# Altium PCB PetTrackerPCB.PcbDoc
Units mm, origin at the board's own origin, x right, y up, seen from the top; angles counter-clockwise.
Board outline 116.71 x 58.42 mm, 4 copper layers (Top Layer, GND Plane, PWR Plane, Bottom Layer), stack 0.868 mm thick; 37 components, 41 nets, 216 pads, 121 vias.
Unrouted connection lines stored in the file: 37.
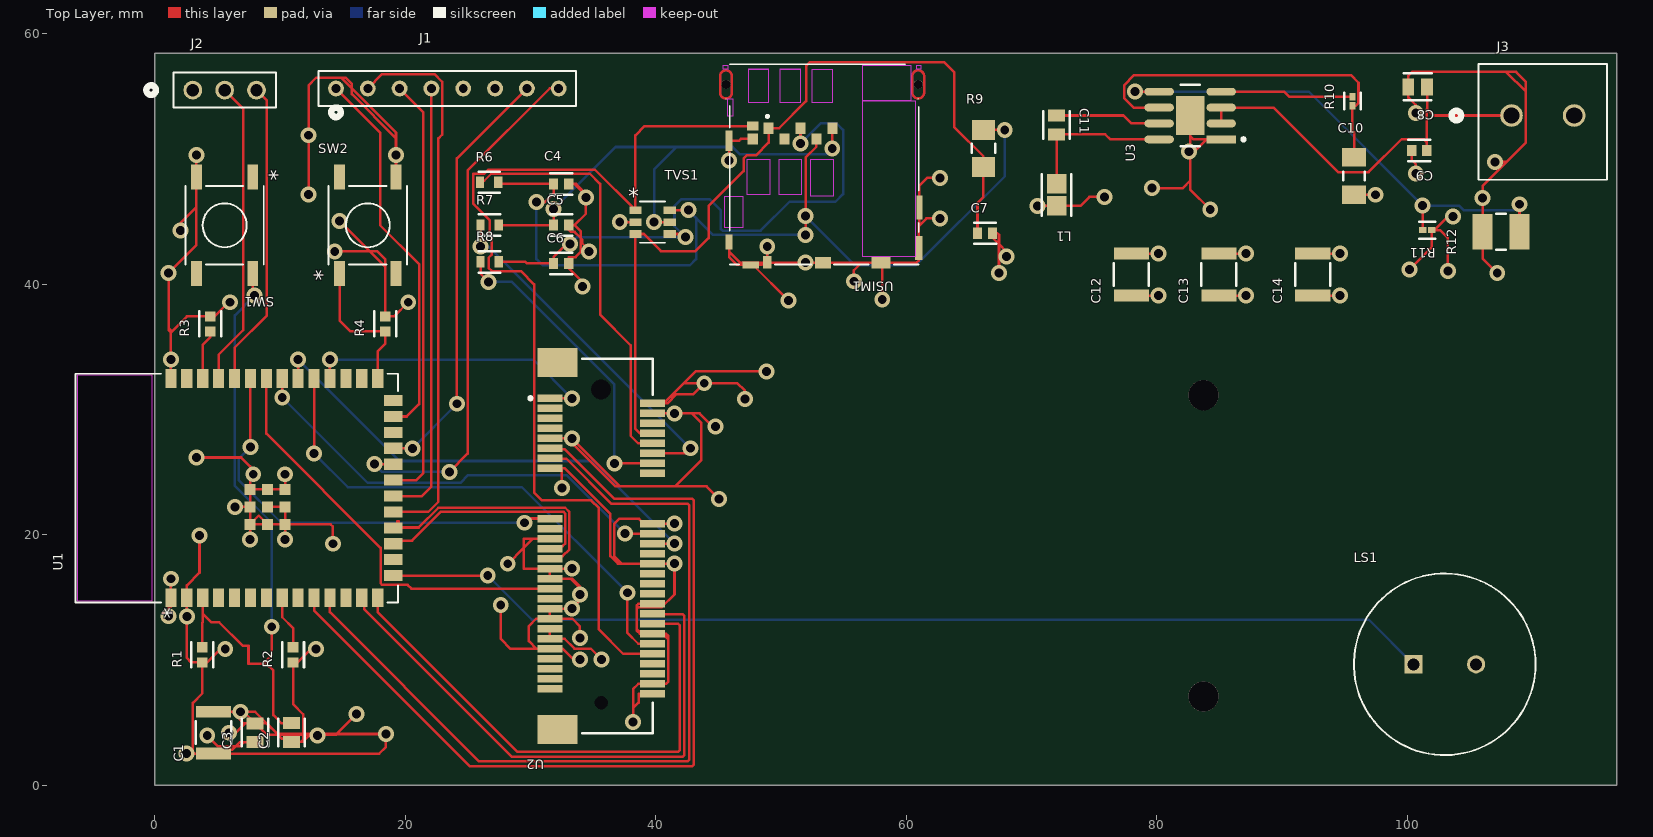
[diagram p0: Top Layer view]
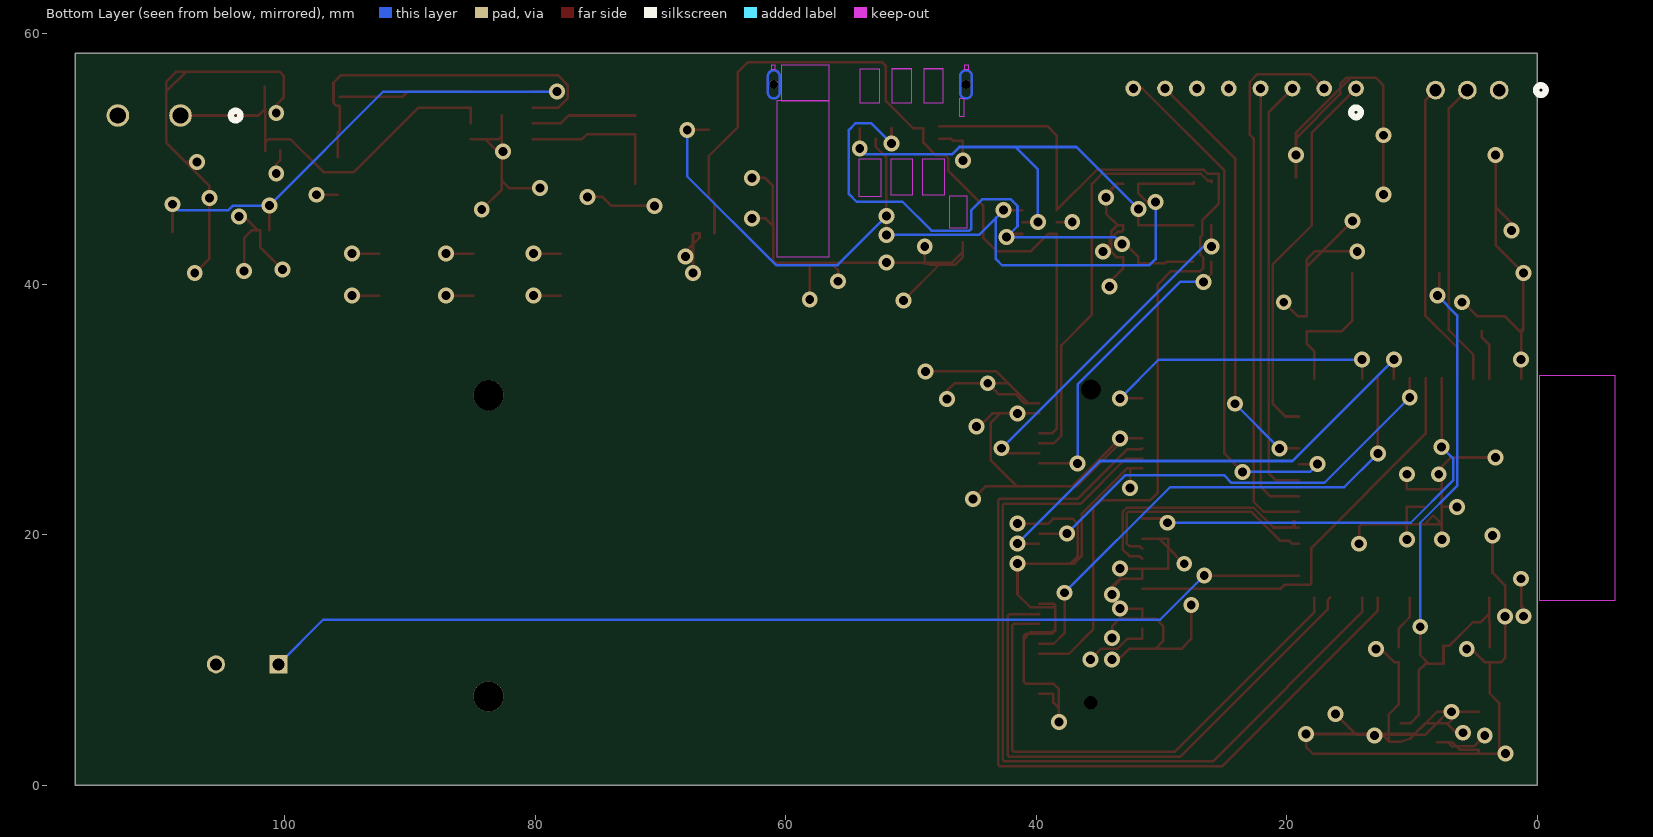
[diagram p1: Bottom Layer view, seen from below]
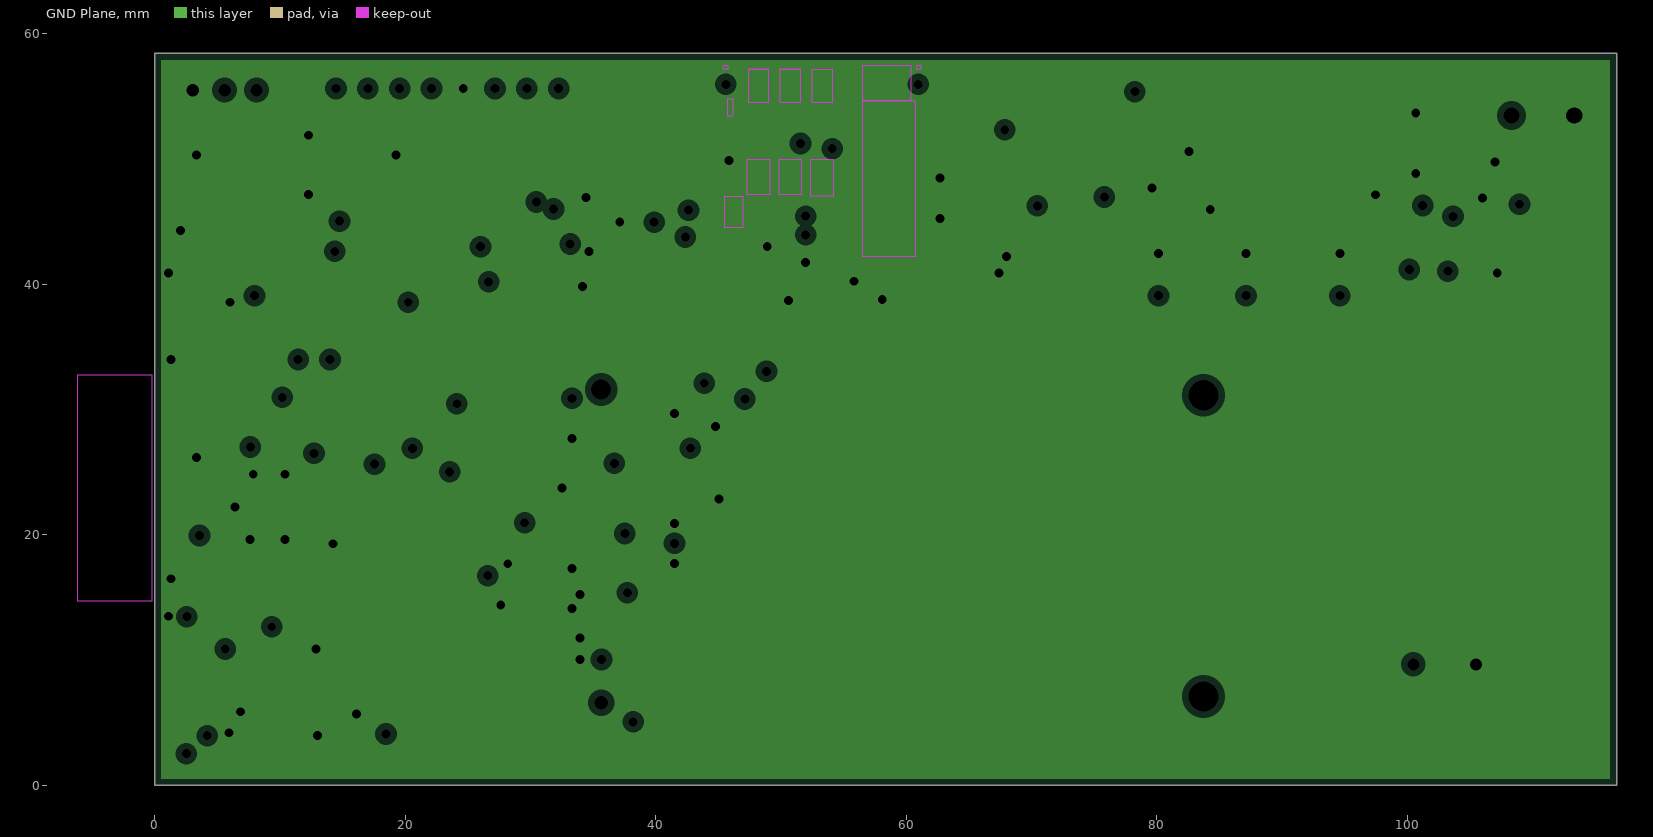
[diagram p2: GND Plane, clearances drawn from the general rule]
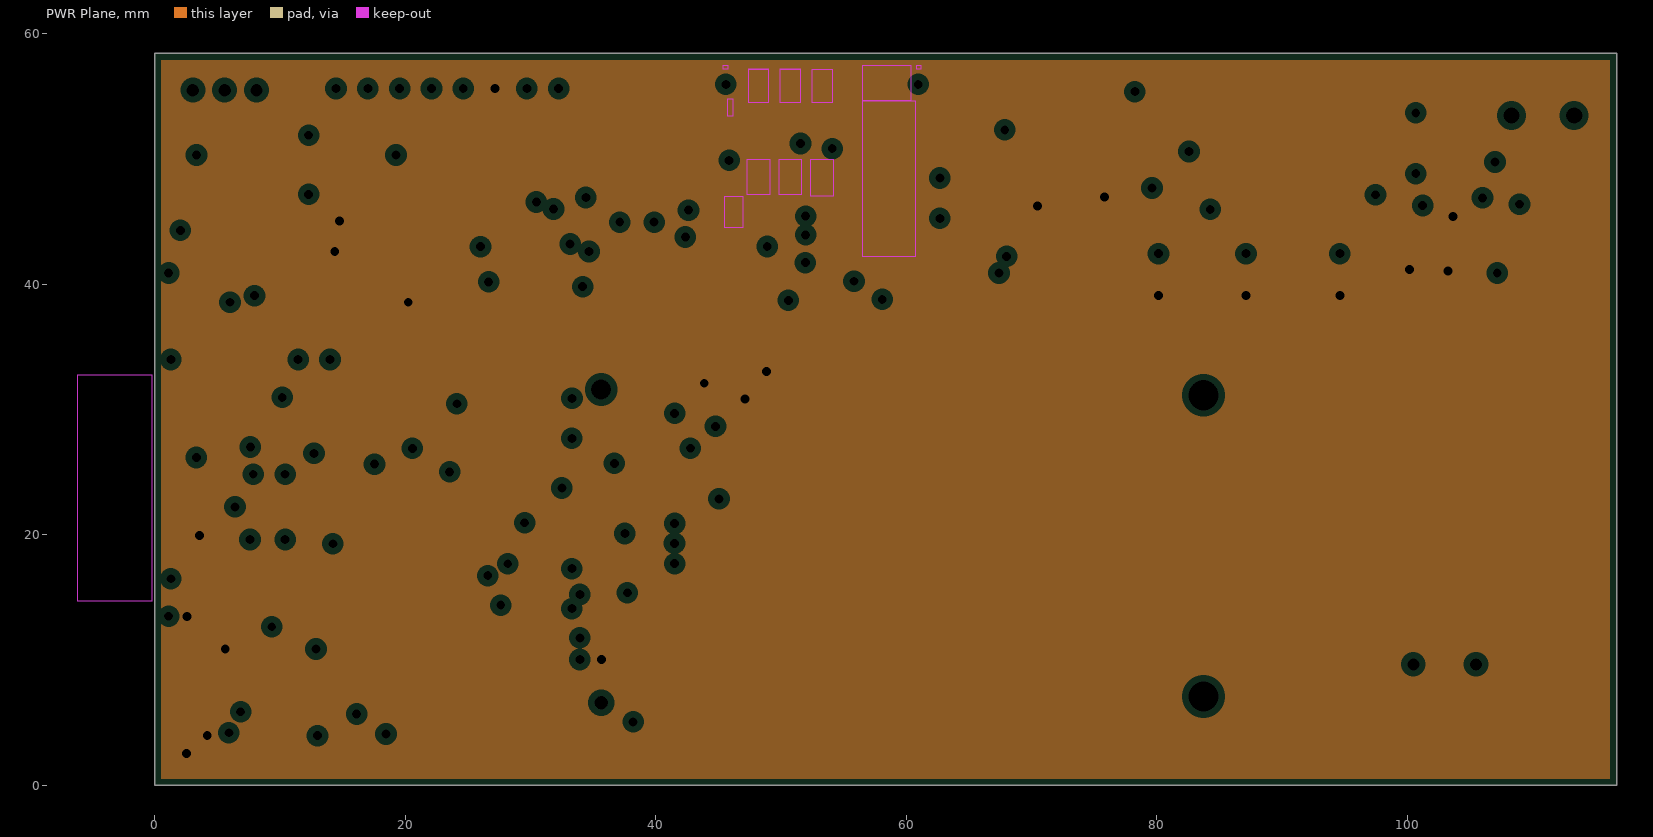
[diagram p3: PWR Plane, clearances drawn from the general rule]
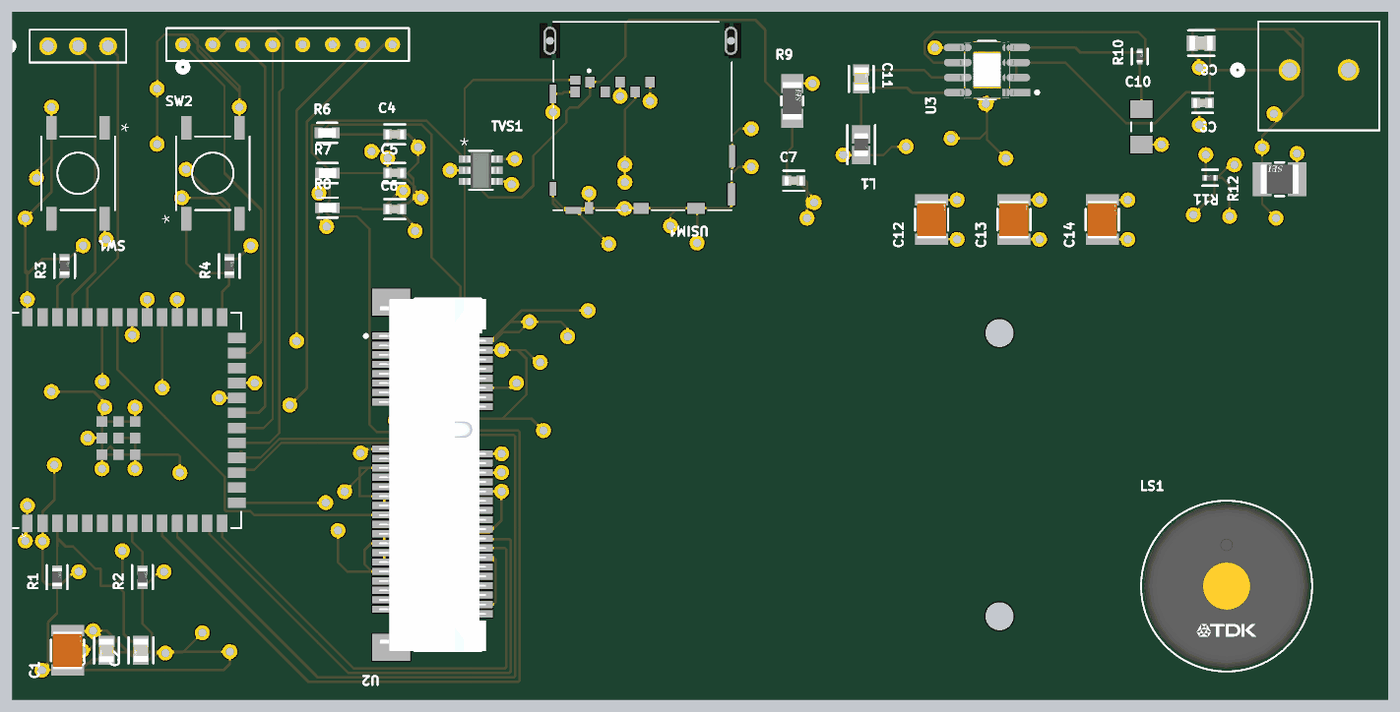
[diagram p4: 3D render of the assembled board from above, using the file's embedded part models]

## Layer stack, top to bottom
Top Solder: solder mask 0.0102, Solder Resist, Dk 3.5
Top Layer: signal copper 0.0356
Dielectric 4: core 0.1016, Core-009, Dk 4.5
Dielectric 2: core 0.1016, Core-009, Dk 4.5
GND Plane: plane copper 0.035, net GND
Dielectric 1: dielectric 0.32, FR-4, Dk 4.8
PWR Plane: plane copper 0.035, net +3V3
Dielectric 3: core 0.1016, Core-009, Dk 4.5
Dielectric 5: core 0.1016, Core-009, Dk 4.5
Bottom Layer: signal copper 0.0356
Bottom Solder: solder mask 0.0102, Solder Resist, Dk 3.5

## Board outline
0,0 116.713,0 116.713,58.42 0,58.42

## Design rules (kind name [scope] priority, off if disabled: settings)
Clearance [All] p1: gap=0.127 ignorepadtopadclearanceinfootprint=FALSE
Height [All] p1 off: minheight=0 maxheight=25.4 prefheight=12.7
PlaneClearance [All] p1: clearance=0.508
PlaneConnect [All] p1: planeconnectstyle=Relief reliefexpansion=0.508 reliefentries=4 reliefconductorwidth=0.254 reliefairgap=0.254
PolygonConnect [All] p1: connectstyle=Relief reliefconductorwidth=0.254 reliefentries=4 polygonreliefangle="90 Angle" airgapwidth=0.254
RoutingVias [All] p1: holewidth=0.711 width=1.27 viastyle="Through Hole" minholewidth=0.711 minwidth=1.27 maxholewidth=0.711 maxwidth=1.27
SolderMaskExpansion [All] p1: expansion=0.102 istentingtop=FALSE
SupplyNets "Schematic Supply Nets_2" [InNet('GND')] p1: voltage=0.000
SupplyNets "Schematic Supply Nets_1" [InNet('Vin')] p2: voltage=0.000
SupplyNets "Schematic Supply Nets" [InNet('+3V3')] p3: voltage=0.000
Width [All] p1: maxlimit=25.4 minlimit=0.127 preferedwidth=0.203
27 further rules are at their usual default settings.

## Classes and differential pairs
component class PowerSupply: C8 C9 C10 C11 C12 C13 C14 CBOOT CHF CIN Cout CVCC J3 L L1 R10 R11 R12 RFBB RFBT U3
component class EC25: C4 C5 C6 C7 CRF1 CRF2 CRF3 CRF4 R6 R7 R8 R9 RDB1 RDB2 RDB3 RS1 TVS1 "TVS Array" U2 USIM1 "USIM Connector"
component class Dataflow: C1 C2 C3 "Camera Interface" J1 J2 LS1 R1 R2 R3 R4 RDB RPU1 S2 SW1 SW2 U1 "USB Connector"

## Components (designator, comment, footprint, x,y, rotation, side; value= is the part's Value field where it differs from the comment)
C1 "22uF" FP-C3225-250-0_4-IPC_B 4.699,4.191 r90 top
C2 "0.1uF" FP-C0805C104M5UACTU-MFG 10.922,4.203 r90 top
C3 "0.1uF" FP-C0805C104M5UACTU-MFG 8.001,4.191 r90 top
C4 "0.1uF" FP-C0603C-CF-MFG 32.447,48.006 r0 top value="0.10 μF"
C5 "0.1uF" FP-C0603C-CF-MFG 32.447,44.72 r0 top value="0.10 μF"
C6 "0.1uF" FP-C0603C-CF-MFG 32.447,41.656 r0 top value="0.10 μF"
C7 "0.1uF" FP-C0603C-CF-MFG 66.294,44.069 r0 top value="0.10 μF"
C8 "10uF" FP-C0805C-DG-MFG 100.838,55.753 r180 top
C9 "0.22uF" FP-C0603C-CF-MFG 100.965,50.673 r180 top value="0.22 μF"
C10 "1uF" CAPC3216X180X50ML20T25 95.758,48.641 r90 top
C11 "0.1uF" FP-C0805C104M5UACTU-MFG 72.009,52.717 r270 top
C12 "22uF" FP-C3225-250-0_4-IPC_B 77.978,40.767 r90 top
C13 "22uF" FP-C3225-250-0_4-IPC_B 84.963,40.767 r90 top
C14 "22uF" FP-C3225-250-0_4-IPC_B 92.456,40.767 r90 top
J1 "TS-108-T-A" CON8_1X8_TU_HTS_SAI 23.368,55.626 r0 top
J2 "PREC003SAAN-RC" CONN_PREC003SAAN-RC_SUL 3.048,55.499 r0 top
J3 "1935161" CONN_1935161_PXC 108.331,53.467 r0 top value=10uF
L1 "6.8uH" FP-MLZ2012-0_85-IPC_A 72.009,47.13 r270 top
LS1 "PS1440P02BT" FP-PS1440P02BT-MFG 102.997,9.652 r0 top
R1 "10kΩ" FP-RMCF0603-IPC_C 3.81,10.414 r90 top
R2 "10kΩ" FP-RMCF0603-IPC_C 11.049,10.414 r90 top
R3 "10kΩ" FP-RMCF0603-IPC_C 4.445,36.83 r90 top
R4 "10kΩ" FP-RMCF0603-IPC_C 18.415,36.83 r90 top
R6 "0Ω" FP-RMCF0603-MFG 26.707,48.133 r0 top value=0mΩ
R7 "0Ω" FP-RMCF0603-MFG 26.744,44.718 r0 top value=0mΩ
R8 "0Ω" FP-RMCF0603-MFG 26.744,41.783 r0 top value=0mΩ
R9 "15kΩ" FP-RMCF1206-IPC_A 66.167,50.848 r90 top
R10 "100kΩ" FP-RMCF0402-IPC_C 95.631,54.61 r90 top
R11 "100kΩ" FP-RMCF0402-IPC_C 101.6,44.323 r180 top
R12 "3.3kΩ" FP-RMCF1210-IPC_A 107.49,44.196 r180 top
SW1 "PTS645SL43SMTR92LFS" PTS645SL43SMTR92LFS_CNK 5.588,44.704 r270 top
SW2 "PTS645SL43SMTR92LFS" PTS645SL43SMTR92LFS_CNK 17.018,44.704 r90 top
TVS1 "AQRV05-4HTG" SOT23-6_LTF 39.751,44.958 r0 top
U1 "ESP32-S2-SOLO-N4R2" MOD41_ESP32-S2-SOLO_EXP 6.557,23.722 r90 top
U2 "2041119-1" TECO-2041119-1_3_V 35.651,19.092 r270 top
U3 "LMR33640ADDAR" FP-DDA0008J-IPC_A 82.677,53.467 r180 top
USIM1 "2174803-2" CONN_2174803-2 50.927,51.151 r180 top

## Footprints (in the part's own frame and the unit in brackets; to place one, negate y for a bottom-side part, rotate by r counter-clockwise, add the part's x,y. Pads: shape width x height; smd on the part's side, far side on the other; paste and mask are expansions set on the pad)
CAPC3216X180X50ML20T25 [mm] "Chip Capacitor, 2-Leads, Body 3.40x1.80mm, IPC Low Density"
  rect 1.5x1.9 smd: 1(-1.5,0) 2(1.5,0)
  silkscreen extent -0.35,-0.85 0.35,0.85, body extent -1.7,-0.9 1.7,0.9, height 1.8
CON8_1X8_TU_HTS_SAI [mil]
  round 50 / inner round 60 / far side round 50 hole 28 paste-99999 mask+0: 1(-350,0) 2(-250,0) 3(-150,0) 4(-50,0) 5(50,0) 6(150,0) 7(250,0) 8(350,0)
  silkscreen extent -405,-90 405,55
CONN_1935161_PXC [mil]
  round 71 / inner round 60 / far side round 71 hole 51 paste-99999 mask+0: 1(0,0) 2(196.85,0)
  silkscreen extent -188,-202 300,162
CONN_2174803-2 [mm]
  rect 0.8x0.9 smd: C1(1.905,-1.3) C2(-0.635,-1.3) C3(-3.175,-1.3) C5(3.175,-0.45) C6(0.635,-0.45) C7(-1.905,-0.45)
  rect 0.1x0.1 smd paste-1 mask+0: C8(5.315,-3.657) C17(-10.035,-3.657)
  rect 0.54x1.6 smd: C9(5.065,-0.3)
  rect 0.54x1.17 smd: C10(5.065,7.785)
  rect 1.33x0.55 smd: C11(3.33,9.605)
  rect 0.7x0.98 smd: C12(2.015,9.39)
  rect 1.3x0.91 smd: C13(-2.435,9.425)
  rect 1.53x0.91 smd: C14(-7.07,9.425)
  rect 0.6x1.9 smd: C15(-10.085,8.25)
  rect 0.5x1.9 smd: C16(-10.135,5.02)
  rect 0.9x0.75 smd: SW(3.175,-1.475)
  round 0.7 hole 0.7 unplated: ""(-10.035,-4.8) ""(5.315,-4.8)
  Top Layer region: 123 vertices and 1 holes, not listed, extent 4.765,-6 5.865,-3.6
  Top Layer region: 124 vertices and 1 holes, not listed, extent -10.585,-6 -9.485,-3.6
  Bottom Layer region: 123 vertices and 1 holes, not listed, extent 4.765,-6 5.865,-3.6
  Bottom Layer region: 124 vertices and 1 holes, not listed, extent -10.585,-6 -9.485,-3.6
  Keep-Out Layer region: -5.624,-3.502 -9.806,-3.502 -9.806,8.97 -5.624,8.97
  Keep-Out Layer region: -5.624,-6.326 -9.458,-6.326 -9.458,-3.5 -5.624,-3.5
  Keep-Out Layer region: -1.565,-6.021 -3.155,-6.021 -3.155,-3.35 -1.565,-3.35
  Keep-Out Layer region: 0.975,-6.024 -0.615,-6.024 -0.615,-3.35 0.975,-3.35
  Keep-Out Layer region: 3.515,-6.031 1.928,-6.031 1.928,-3.35 3.515,-3.35
  Keep-Out Layer region: 5.515,-6.332 5.175,-6.332 5.175,-6.02 5.515,-6.02
  Keep-Out Layer region: 5.165,-3.65 4.765,-3.65 4.765,-2.25 5.165,-2.25
  Keep-Out Layer region: -1.465,1.172 -3.261,1.172 -3.261,4.12 -1.465,4.12
  Keep-Out Layer region: 1.075,1.171 -0.716,1.171 -0.716,4 1.075,4
  Keep-Out Layer region: 3.615,1.172 1.828,1.172 1.828,4 3.615,4
  Keep-Out Layer region: 5.42,4.127 3.977,4.127 3.977,6.63 5.42,6.63
  Keep-Out Layer region: -9.9,-6.323 -10.24,-6.323 -10.24,-6.02 -9.9,-6.02
  Keep-Out Layer region: -5.624,-3.505 -9.815,-3.505 -9.815,8.97 -5.624,8.97
  Keep-Out Layer region: -5.624,-6.322 -9.452,-6.322 -9.452,-3.5 -5.624,-3.5
  Keep-Out Layer region: -1.565,-6.027 -3.159,-6.027 -3.159,-3.35 -1.565,-3.35
  Keep-Out Layer region: 0.975,-6.023 -0.615,-6.023 -0.615,-3.35 0.975,-3.35
  Keep-Out Layer region: 3.515,-6.021 1.925,-6.021 1.925,-3.35 3.515,-3.35
  Keep-Out Layer region: 5.515,-6.326 5.17,-6.326 5.17,-6.02 5.515,-6.02
  Keep-Out Layer region: 5.165,-3.653 4.768,-3.653 4.768,-2.25 5.165,-2.25
  Keep-Out Layer region: -1.465,1.172 -3.261,1.172 -3.261,4.12 -1.465,4.12
  Keep-Out Layer region: 1.075,1.171 -0.716,1.171 -0.716,4 1.075,4
  Keep-Out Layer region: 3.615,1.171 1.826,1.171 1.826,4 3.615,4
  Keep-Out Layer region: 5.42,4.123 3.973,4.123 3.973,6.63 5.42,6.63
  Keep-Out Layer region: -9.9,-6.332 -10.255,-6.332 -10.255,-6.02 -9.9,-6.02
  Keep-Out Layer region: -5.624,-3.506 -9.818,-3.506 -9.818,8.97 -5.624,8.97
  Keep-Out Layer region: -5.624,-6.322 -9.454,-6.322 -9.454,-3.5 -5.624,-3.5
  Keep-Out Layer region: -1.565,-6.024 -3.157,-6.024 -3.157,-3.35 -1.565,-3.35
  Keep-Out Layer region: 0.975,-6.03 -0.616,-6.03 -0.616,-3.35 0.975,-3.35
  Keep-Out Layer region: 3.515,-6.028 1.927,-6.028 1.927,-3.35 3.515,-3.35
  Keep-Out Layer region: 5.515,-6.332 5.175,-6.332 5.175,-6.02 5.515,-6.02
  Keep-Out Layer region: 5.165,-3.653 4.769,-3.653 4.769,-2.25 5.165,-2.25
  Keep-Out Layer region: -1.465,1.172 -3.261,1.172 -3.261,4.12 -1.465,4.12
  Keep-Out Layer region: 1.075,1.171 -0.715,1.171 -0.715,4 1.075,4
  Keep-Out Layer region: 3.615,1.17 1.825,1.17 1.825,4 3.615,4
  Keep-Out Layer region: 5.42,4.121 3.971,4.121 3.971,6.63 5.42,6.63
  Keep-Out Layer region: -9.9,-6.332 -10.255,-6.332 -10.255,-6.02 -9.9,-6.02
  silkscreen extent -10.09,-6.4 5.01,9.58
CONN_PREC003SAAN-RC_SUL [mil]
  round 59 / inner round 60 / far side round 59 hole 39 paste-99999 mask+0: 1(0,0) 2(100,0) 3(200,0)
  silkscreen extent -146,-55 261,55
FP-C0603C-CF-MFG [mm]
  rect 0.75x0.9 smd paste+0 mask+0: 1(-0.6,0) 2(0.6,0)
  silkscreen extent -0.88,-0.85 0.88,0.85, body extent -1.2,-0.6 1.2,0.6, height 0.25
FP-C0805C104M5UACTU-MFG [mm]
  rect 0.95x1.35 smd paste+0 mask+0: 1(-0.75,0) 2(0.75,0)
  silkscreen extent -1.1,-1.05 1.1,1.05, body extent -1.4,-0.85 1.4,0.85, height 0.25
FP-C0805C-DG-MFG [mm]
  rect 0.95x1.35 smd paste+0 mask+0: 1(-0.75,0) 2(0.75,0)
  silkscreen extent -1.11,-1.08 1.1,1.07, body extent -1.4,-0.85 1.4,0.85, height 0.25
FP-C3225-250-0_4-IPC_B [mm]
  rect 0.953x2.804 smd paste+0 mask+0: 1(-1.675,0) 2(1.675,0)
  silkscreen extent -0.9,-1.4 0.9,1.4, body extent -2.4,-1.65 2.4,1.65, height 0.25
FP-DDA0008J-IPC_A [mm]
  rect 2.353x0.622 smd paste+0 mask+0: 1(-2.477,1.905)
  rrect100% 2.353x0.622 smd paste+0 mask+0: 2(-2.477,0.635) 3(-2.477,-0.635) 4(-2.477,-1.905) 5(2.477,-1.905) 6(2.477,-0.635) 7(2.477,0.635) 8(2.477,1.905)
  rect 2.3x3.1 smd paste-1000 mask+0: 9(0,0)
  silkscreen extent -4.38,-2.45 0.75,2.45, body extent -4.15,-2.95 4.15,2.95, height 0.25
FP-MLZ2012-0_85-IPC_A [mm]
  rect 1.554x1.556 smd paste+0 mask+0: 1(-0.876,0) 2(0.876,0)
  silkscreen extent -1.65,-1.18 1.65,1.18, body extent -2.15,-1.28 2.15,1.28, height 0.25
FP-PS1440P02BT-MFG [mm]
  rect 1.45x1.45 hole 0.95 paste-2539.97 mask+0: 1(-2.5,0)
  round 1.45 hole 0.95 paste-2539.97 mask+0: 2(2.5,0)
  silkscreen extent -7.25,-7.25 7.25,7.25, body extent -7.35,-7.35 7.35,7.35, height 0.25
FP-RMCF0402-IPC_C [mm]
  rect 0.581x0.472 smd paste+0 mask+0: 1(-0.366,0) 2(0.366,0)
  silkscreen extent -0.66,-0.67 0.66,0.67, body extent -0.76,-0.38 0.76,0.38, height 0.25
FP-RMCF0603-IPC_C [mm]
  rect 0.806x0.858 smd paste+0 mask+0: 1(-0.601,0) 2(0.601,0)
  silkscreen extent -1,-0.87 1,0.87, body extent -1.1,-0.58 1.1,0.58, height 0.25
FP-RMCF0603-MFG [mm]
  rect 0.65x0.9 smd paste+0 mask+0: 1(-0.725,0) 2(0.725,0)
  silkscreen extent -0.85,-0.85 0.85,0.85, body extent -1.15,-0.58 1.15,0.58, height 0.25
FP-RMCF1206-IPC_A [mm]
  rect 1.604x1.858 smd paste+0 mask+0: 1(-1.476,0) 2(1.476,0)
  silkscreen extent -0.37,-0.93 0.37,0.93, body extent -2.78,-1.43 2.78,1.43, height 0.25
FP-RMCF1210-IPC_A [mm]
  rect 1.604x2.855 smd paste+0 mask+0: 1(-1.476,0) 2(1.476,0)
  silkscreen extent -0.37,-1.43 0.37,1.43, body extent -2.78,-1.93 2.78,1.93, height 0.25
MOD41_ESP32-S2-SOLO_EXP [mil]
  rect 59x35 smd paste+0 mask+0: 1(-344.49,207.09) 2(-344.49,157.09) 3(-344.49,107.09) 4(-344.49,57.09) 5(-344.49,7.09) 6(-344.49,-42.91) 7(-344.49,-92.91) 8(-344.49,-142.91) 9(-344.49,-192.91) 10(-344.49,-242.91) 11(-344.49,-292.91) 12(-344.49,-342.91) 13(-344.49,-392.91) 14(-344.49,-442.91) 27(344.49,-442.91) 28(344.49,-392.91) 29(344.49,-342.91) 30(344.49,-292.91) 31(344.49,-242.91) 32(344.49,-192.91) 33(344.49,-142.91) 34(344.49,-92.91) 35(344.49,-42.91) 36(344.49,7.09) 37(344.49,57.09) 38(344.49,107.09) 39(344.49,157.09) 40(344.49,207.09)
  rect 35x59 smd paste+0 mask+0: 15(-275,-492.13) 16(-225,-492.13) 17(-175,-492.13) 18(-125,-492.13) 19(-75,-492.13) 20(-25,-492.13) 21(25,-492.13) 22(75,-492.13) 23(125,-492.13) 24(175,-492.13) 25(225,-492.13) 26(275,-492.13)
  rect 35x35 smd paste+0 mask+0: 41(-59.05,-96.85) 42(-114.17,-41.73) 43(-114.17,-96.85) 44(-114.17,-151.97) 45(-59.05,-151.97) 46(-3.94,-151.97) 47(-3.94,-96.85) 48(-3.94,-41.73) 49(-59.05,-41.73)
  Keep-Out Layer region: 354.5,502 -354.5,502 -354.5,266 354.5,266
  silkscreen extent -359,-507 360,507
PTS645SL43SMTR92LFS_CNK [mil]
  rect 79x34 smd paste+0 mask+0: 1(-151.5,88.58) 2(151.5,88.58) 3(-151.5,-88.58) 4(151.5,-88.58)
  silkscreen extent -123,-123 123,123
SOT23-6_LTF [mil]
  rect 38.5x24 smd paste+0 mask+0: 1(-53.75,37.4) 2(-53.75,0) 3(-53.75,-37.4) 4(53.75,-37.4) 5(53.75,0) 6(53.75,37.4)
  silkscreen extent -40,-65 40,65, body extent -59,-60 59,60, height 57
TECO-2041119-1_3_V [mm] "Connector, 52-Leads, Body 29.9x8.2mm, Pitch 0.4mm"
  rect 0.6x2 smd: 1(-11.8,-4.1) 2(-11.4,4.1) 3(-11,-4.1) 4(-10.6,4.1) 5(-10.2,-4.1) 6(-9.8,4.1) 7(-9.4,-4.1) 8(-9,4.1) 9(-8.6,-4.1) 10(-8.2,4.1) 11(-7.8,-4.1) 12(-7.4,4.1) 13(-7,-4.1) 14(-6.6,4.1) 15(-6.2,-4.1) 16(-5.8,4.1) 17(-2.2,-4.1) 18(-1.8,4.1) 19(-1.4,-4.1) 20(-1,4.1) 21(-0.6,-4.1) 22(-0.2,4.1) 23(0.2,-4.1) 24(0.6,4.1) 25(1,-4.1) 26(1.4,4.1) 27(1.8,-4.1) 28(2.2,4.1) 29(2.6,-4.1) 30(3,4.1) 31(3.4,-4.1) 32(3.8,4.1) 33(4.2,-4.1) 34(4.6,4.1) 35(5,-4.1) 36(5.4,4.1) 37(5.8,-4.1) 38(6.2,4.1) 39(6.6,-4.1) 40(7,4.1) 41(7.4,-4.1) 42(7.8,4.1) 43(8.2,-4.1) 44(8.6,4.1) 45(9,-4.1) 46(9.4,4.1) 47(9.8,-4.1) 48(10.2,4.1) 49(10.6,-4.1) 50(11,4.1) 51(11.4,-4.1) 52(11.8,4.1)
  round 1.3 hole 1.6 unplated: MH1(-12.5,0)
  round 0.9 hole 1.1 unplated: MH2(12.5,0)
  rect 2.3x3.2 smd: MP1(-14.65,-3.5) MP2(14.65,-3.5)
  silkscreen extent -14.95,-5.77 14.95,4.1, body extent -14.95,-4.54 14.95,4.55, height 4

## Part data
C1 C12 C13 C14: library part CMP-2000-06052-2, "C3225X7R1C226M250AC Multilayer Ceramic Capacitors 22uF ±20% 16V X7R SMD 1210", Case Code (Imperial)=1210, Case Code (Metric)=3225, Dielectric=X7R, Dielectric Material=Ceramic, Max Operating Temperature=125°C, Min Operating Temperature=-55°C, Package Quantity=1, Tolerance=20%, Voltage Rating=16V
C2 C3 C11: library part CMP-2007-03742-2, "C0805C104M5UACTU CAP CER 0.1UF 50V Z5U 0805", Capacitance=100nF, Case Code (Imperial)=0805, Case Code (Metric)=2012, Dielectric=Z5U, Dielectric Material=Ceramic, Max Operating Temperature=85°C, Min Operating Temperature=10°C, Package Quantity=1, Tolerance=20%, Voltage=50V
C4 C5 C6 C7: library part CMP-2006-03056-2, "C0603C104J5RACTU CAP CER 0.1UF 50V 5% X7R 0603", Capacitance="0.10 μF", Manufacturer=KEMET, Manufacturer Part Number=C0603C104J5RACTU, Package=C0603C-CF, Temperature="-55°C to +125°C", Temperature Characteristic=X7R, Temperature Coefficient=30ppm/°C, Temperature Range High=+125°C, Temperature Range Low=-55°C, Tolerance=0.05, Voltage Rating="50 V"
C8: library part CMP-2007-03243-2, "C0805C106K8PACTU CAP CER 10UF 10V X5R 0805", 3DS Part Number=220-00001, Manufacturer=Kemet, Manufacturer Part Number=C0805C106K8PACTU, Package=C0805C-DG, Temperature="-55°C to +85°C", Temperature Characteristic=X5R, Temperature Coefficient=15%, Temperature Range High=+85°C, Temperature Range Low=-55°C, Tolerance=10%, Voltage=10V
C9: library part CMP-2006-03146-2, "C0603C224K3RACTU CAP CER 0.22UF 25V 10% X7R 0603", Capacitance="0.22 μF", Manufacturer=KEMET, Manufacturer Part Number=C0603C224K3RACTU, Package=C0603C-CF, Temperature="-55°C to +125°C", Temperature Characteristic=X7R, Temperature Coefficient=30ppm/°C, Temperature Range High=+125°C, Temperature Range Low=-55°C, Tolerance=0.1, Voltage Rating="25 V"
C10: library part CMP-2000-04991-1, "C1206C105K3RACTU Chip Capacitor, 1 uF, +/- 10%, 25 V, -55 to 125 degC, 1206 (3216 Metric), RoHS, Tape and Reel", Capacitance - nF=1000nF, Case Code - in=1206, Case Code - mm=3216, Case Height=1.6mm, Case Length=3.2mm, Dielectric=X7R, Manufacturer=Kemet, Maximum Operating Temperature=+125C, Minimum Operating Temperature=-55C, Operating Temperature Range=-55Cto+125C, Package / Case=1206(3216metric), Package Description="2-Pin Surface Mount Device, Body 3.2 x 1.6 mm", Temperature Coefficient / Code=+/-15%, Tolerance=10%, Voltage Rating=25V
J1: "No Description Available", Mfr_Name="Samtec Inc"
J2: "No Description Available", Mfr_Name=Sullins
J3: "Ceramic Capacitor, Multilayer, Ceramic, 16V, 10% +Tol, 10% -Tol, X5R, 15% TC, 10uF, Surface Mount, 0805", Capacitor Type=Ceramic, Case/Package=0805, Manufacturer=Samsung, Manufacturer Part Number=CL21A106KOQNNNE, Max Operating Temperature=85°C, Mfr_Name="Phoenix Contact", Min Operating Temperature=-55°C, Package Shape=Rectangular, Package Style=SMTMeter, Rated DC Voltage (URdc)=16V, Supplier Part Number=1276-1096-1-ND, Temperature Characteristics Code=X5R, Tolerance  (fill in as +-)=10%
L1: library part CMP-08253-000092-1, "MLZ2012N6R8LT000 Shielded Multilayer Inductor 6.8uH ±20% 550mA 325mΩ SMD 0805", Case Code (Imperial)=0805, Case Code (Metric)=2012, Current Rating=550mA, DC Resistance (DCR)=250mR, Max Operating Temperature=125°C, Min Operating Temperature=-55°C, Package Quantity=1, Saturation Current=110mA, Self Resonant Frequency=60MHz, Test Frequency=2MHz, Tolerance=20%
LS1: library part CMP-08413-000003-1, "AUDIO PIEZO TRANSDUCER 30V TH", Frequency=4kHz, Max Operating Temperature=70°C, Min Operating Temperature=-10°C, Operating Supply Voltage=3V, Package Quantity=350
R1 R2 R3 R4: library part CMP-26527-002098-1, "RMCF0603JT10K0 10kΩ ±5% 0.1W 0603 Thick Film Chip Resistor AEC-Q200 compliant", Case Code (Imperial)=0603, Case Code (Metric)=1608, Max Operating Temperature=155°C, Max Power Dissipation=100mW, Min Operating Temperature=-55°C, Resistance=10kR, Resistor Type="Thick Film", Temperature Coefficient=100ppm/°C, Tolerance=5%
R6 R7 R8: library part CMP-26527-000011-1, "RMCF0603ZT0R00 RES 0 OHM JUMPER 1/10W 0603", Manufacturer=Stackpole, Manufacturer Part Number=RMCF0603ZT0R00, Package=RMCF0603, Power Rating=0.1W, Resistance=0mΩ, Temperature="-55°C to +155°C", Temperature Range High=+155°C, Temperature Range Low=-55°C, Voltage Rating=75V
R9: library part CMP-26527-001400-1, "RMCF1206JT15K0 15kΩ ±5% 0.25W 1206 Thick Film Chip Resistor AEC-Q200 compliant", Case Code (Imperial)=1206, Case Code (Metric)=3216, Max Operating Temperature=155°C, Max Power Dissipation=250mW, Min Operating Temperature=-55°C, Resistance=15kR, Resistor Type="Thick Film", Temperature Coefficient=200ppm/°C, Tolerance=5%
R10 R11: library part CMP-2000-06984-2, "RMCF0402FT100K 100kΩ ±1% 0.063W 0402 Thick Film Chip Resistor AEC-Q200 compliant", Case Code (Imperial)=0402, Case Code (Metric)=1005, Max Operating Temperature=155°C, Max Power Dissipation=63mW, Min Operating Temperature=-55°C, Power Rating=62.5mW, Resistance=100kR, Resistor Type="Thick Film", Temperature Coefficient=100ppm/°C, Tolerance=1%
R12: library part CMP-26527-001928-1, "RMCF1210JT3K30 3.3kΩ ±5% 0.5W 1210 Thick Film Chip Resistor AEC-Q200 compliant", Case/Package=1210, Max Operating Temperature=155°C, Max Power Dissipation=333mW, Min Operating Temperature=-55°C, Resistance=3.3kR, Resistor Type="Thick Film", Temperature Coefficient=200ppm/°C, Tolerance=5%
SW1 SW2: "No Description Available", Mfr_Name="C&K Components"
TVS1: "No Description Available", Mfr_Name="Littelfuse Inc"
U1: "No Description Available", Mfr_Name="Espressif Systems"
U2: library part CMP-2011-00000-2, "mSATA & PCI Express Mini Card Connector, Pitch 0.4 mm, 52 Position, Height 4 mm, RoHS, Tape and Reel", Case\Package=SMD, Housing Colour=Black, Manufacturer="TE Connectivity", Package Description="mSATA & PCI Express Mini Card Connector, Pitch 0.4 mm, 52 Position, Height 4 mm", Package Reference=2041119-1_3
U3: library part CMP-04918-000399-1, "36V 4A 400KHZ REGULATOR"
USIM1: "CONNECTOR, SIM SOCKET, 6POS, 2.54MM; Connector Type:SIM Socket; Series:2174803;", Package=None, Voltage_Rating="10 VAC"

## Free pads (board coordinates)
  round 2.4 hole 2.4 unplated: 2(83.737,31.136) 3(83.737,7.091)

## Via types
v1: diameter 1.27, hole 0.711, Top Layer to Bottom Layer, 121 vias

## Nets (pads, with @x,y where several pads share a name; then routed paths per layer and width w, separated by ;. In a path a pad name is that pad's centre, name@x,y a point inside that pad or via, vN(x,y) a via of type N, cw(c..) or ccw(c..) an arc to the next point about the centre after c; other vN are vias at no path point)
+3V3: C1.1 C3.1 C12.1 C13.1 C14.1 J1.6 L1.2 R1.1 R4.2 R11.1 U1.2 U2.2 U2.39 U2.41 U2.52 | length 142.7
  Top Layer w0.203: v1(2.535,2.516) 3.175,2.516 ; U1.2 v1(2.567,13.461) 2.567,10.16 2.914,9.813 ; v1(3.581,19.939) 3.581,16.967 2.565,15.951 ; v1(4.198,3.962) 5.061,3.099 6.465,3.099 ; v1(5.64,10.871) 5.241,10.871 4.183,9.813 R1.1 ; C3.1 7.146,3.441 ; v1(14.376,42.621) 17.78,42.621 18.415,41.986 18.415,41.377 ; v1(14.757,45.034) 18.415,41.377 ; v1(18.466,4.089) 18.466,3.048 17.934,2.516 C1.1 ; v1(20.245,38.557) 19.119,37.431 R4.2 18.415,41.377 ; U2.39 U2.39@31.547,12.492 ; v1(35.679,10.041) 34.816,10.904 33.518,10.904 32.731,11.692 U2.41 U2.41@31.547,11.692 ; v1(38.202,5.055) 38.202,6.172 38.633,6.604 38.633,7.292 U2.52 ; U2.2 U2.2@40.64,30.492 ; v1(43.879,32.094) 43.016,31.231 41.669,31.231 40.931,30.492 U2.2@40.64,30.492 ; v1(47.117,30.836) 47.117,31.496 46.507,32.106 ; v1(48.844,33.045) 43.193,33.045 42.254,32.106 ; v1(70.469,46.254) L1.2 73.914,46.254 74.624,46.965 v1(75.819,46.965) ; C12.1 v1(80.142,39.092) ; C13.1 v1(87.127,39.092) ; C14.1 v1(94.62,39.092) ; v1(100.178,41.173) 101.966,42.961 R11.1 R11.1@102.183,44.323 ; v1(103.251,41.046) 103.251,43.688 102.616,44.323 R11.1@102.183,44.323 ; v1(103.657,45.415) 103.275,45.415 R11.1@102.183,44.323 ; 2.565,10.16 2.565,15.951 ; 2.565,10.16 U1.2@2.565,14.972 ; 2.565,10.16 U1.2@2.565,14.972 ; 2.565,10.16 2.565,15.951 ; 2.565,10.16 2.912,9.813 2.914,9.813 ; U1.2@2.565,14.972 2.565,15.951 ; U1.2@2.565,14.972 2.565,15.951 ; 2.914,9.813 R1.1 ; 3.175,2.516 C1.1 ; 3.175,2.516 3.048,2.643 3.048,6.579 3.81,7.341 R1.1 ; C1.1 C1.1@4.699,2.819 ; C1.1@4.699,2.819 6.186,2.819 ; C1.1@4.699,2.819 6.186,2.819 ; 6.186,2.819 6.465,3.099 ; 6.465,3.099 6.804,3.099 7.146,3.441 ; 6.465,3.099 6.807,3.441 7.146,3.441 ; U2.41@31.547,11.692 U2.39@31.547,12.492 ; U2.41@31.547,11.692 U2.39@31.547,12.492 ; U2.2@40.64,30.492 42.254,32.106 ; 42.254,32.106 46.507,32.106 ; 42.254,32.106 46.507,32.106
GND: C1.2 C2.1 C3.2 C4.2 C5.2 C6.2 C7.2 C8.2 C9.2 C10.1 C12.2 C13.2 C14.2 J1.5 J2.1 J3.2 LS1.2 R2.1 R3.2 R12.2 SW1.3 SW2.4 TVS1.2 U1.1 U1.40 U1.41 U1.42 U1.43 U1.44 U1.45 U1.46 U1.47 U1.48 U1.49 U2.4 U2.9 U2.15 U2.18 U2.21 U2.26 U2.27 U2.29 U2.34 U2.35 U2.37 U2.40 U2.43 U2.50 U3.1 U3.9 USIM1.C5 USIM1.C8 USIM1.C9 USIM1.C10 USIM1.C11 USIM1.C12 USIM1.C13 USIM1.C14 USIM1.C15 USIM1.C16 USIM1.C17 | length 423.4
  Top Layer w0.203: v1(1.297,16.483) U1.1 U1.1@1.297,14.376 ; U1.40 v1(1.297,33.983) 1.297,36.144 ; v1(2.057,44.298) 2.057,44.871 3.338,46.152 ; v1(3.327,26.162) 6.906,26.162 7.617,25.451 v1@7.617,24.699 ; v1(3.338,50.317) SW1.3 3.338,46.152 ; C1.2 6.187,5.866 ; v1(5.925,4.191) 6.478,4.191 7.228,4.941 ; v1(6.021,38.557) 5.91,38.557 4.784,37.431 R3.2 2.582,37.431 1.297,36.144 ; v1(6.411,22.222) U1.49 ; v1(7.617,19.616) U1.42 ; v1(7.871,24.828) 7.747,24.828 v1@7.617,24.699 ; U1.41 U1.45 10.439,22.2 10.439,20.844 U1.44 ; v1(10.417,19.616) U1.44 ; v1(10.417,24.828) U1.46 U1.47 U1.48 ; v1(12.294,47.168) v1(12.294,51.892) 12.294,55.88 12.903,56.49 ; v1(12.879,10.871) 12.48,10.871 11.422,9.813 R2.1 11.049,6.477 11.862,5.664 11.862,4.039 ; v1(12.998,3.962) 12.324,3.962 11.815,3.453 11.684,3.453 ; v1(14.224,19.279) 14.224,20.65 14.052,20.822 U1.44 ; v1(16.129,5.69) 14.478,4.039 ; v1(18.466,4.089) 9.803,4.089 8.026,5.866 v1@7.112,5.866 ; SW2.4 v1(19.268,50.317) 19.268,51.649 ; v1(27.635,14.376) 27.635,11.684 28.427,10.892 30.48,10.892 ; v1(28.194,17.678) 29.464,18.948 ; U2.21 30.208,19.692 ; U2.15 U2.15@32.512,25.292 ; C4.2 33.528,48.006 ; v1(33.313,17.292) U2.27 U2.27@31.547,17.292 ; v1(33.952,10.041) 33.45,10.041 32.598,10.892 U2.43 30.48,10.892 ; v1(33.952,11.768) 33.952,12.681 33.341,13.292 U2.37 U2.37@31.547,13.292 ; v1(33.952,15.222) v1@33.952,15.756 ; v1(34.174,39.805) 34.174,40.17 33.047,41.297 C6.2 33.047,42.164 ; v1(34.428,46.917) v1@34.417,46.928 ; v1(34.682,42.615) 34.682,42.726 34.138,43.27 34.138,43.565 34.036,43.667 ; v1(37.135,44.958) TVS1.2 ; v1(38.202,5.055) 38.202,7.686 38.608,8.092 U2.50 40.833,8.092 40.996,8.255 40.996,11.684 ; U2.34 38.647,14.492 38.506,14.351 38.506,14.097 ; U2.4 v1(41.513,29.692) 42.901,29.692 ; v1(41.513,17.692) v1@41.148,17.692 ; v1(41.513,20.892) U2.18 39.04,20.892 38.672,21.26 37.084,21.26 36.678,20.853 36.678,18.288 37.274,17.692 ; v1(44.78,28.651) 44.551,28.651 43.51,29.692 42.901,29.692 ; v1(45.06,22.86) 44.069,23.851 41.554,23.851 ; USIM1.C10 45.862,42.6 ; v1(45.862,49.889) USIM1.C9 46.662,51.451 46.812,51.601 USIM1.C5 ; v1(48.912,43.013) USIM1.C12 USIM1.C12@48.912,41.726 ; v1(50.597,38.71) 47.752,41.554 46.472,41.554 45.862,42.164 ; v1(55.831,40.234) 55.831,41.115 56.442,41.726 ; v1(62.687,45.252) 61.623,45.252 61.012,44.641 ; v1(62.687,48.482) 61.673,48.482 61.062,47.871 USIM1.C16 61.062,44.958 61.012,44.908 61.012,44.641 ; v1(68.021,42.218) 68.021,42.583 67.412,43.192 ; C12.2 v1(80.142,42.442) ; v1(79.629,47.676) 82.093,47.676 82.677,48.26 ; v1(82.576,50.597) v1@82.677,50.597 ; U3.9 82.677,51.816 ; v1(84.277,45.974) 82.677,47.574 82.677,48.26 ; C13.2 v1(87.127,42.442) ; U3.1 U3.1@83.987,51.562 ; C14.2 v1(94.62,42.442) ; C10.1 v1(97.47,47.141) ; C9.2 100.365,49.911 100.686,49.59 v1(100.686,48.822) ; v1(100.686,53.677) 100.686,54.306 100.088,54.904 C8.2 100.088,56.642 100.393,56.947 107.899,56.947 ; v1(107.01,49.759) 107.925,49.759 ; v1(107.188,40.894) 106.015,42.067 R12.2 v1(106.015,46.894) 106.015,47.849 107.925,49.759 ; v1(1.118,40.894) 3.338,43.114 3.338,46.152 ; v1(1.118,40.894) 1.118,36.501 1.297,36.322 1.297,36.144 ; v1(1.118,40.894) 1.118,36.324 1.297,36.144 ; U1.1@1.297,14.376 1.297,14.275 1.118,14.095 v1(1.118,13.487) 1.118,14.197 U1.1@1.297,14.376 ; 6.187,5.866 7.112,4.941 ; 6.187,5.866 7.112,4.941 ; 6.187,5.866 v1(6.863,5.866) v1@7.112,5.866 ; 7.112,4.941 7.228,4.941 ; v1@7.112,5.866 C3.2@8.037,4.941 ; v1@7.112,5.866 C3.2@8.037,4.941 ; 7.228,4.941 C3.2 C3.2@8.037,4.941 ; U1.42 U1.43 ; U1.42 8.309,21.514 8.325,21.514 U1.43 ; U1.42 U1.49 ; U1.49 U1.48 ; U1.48 v1@7.617,24.699 ; C3.2@8.037,4.941 8.927,4.941 9.83,4.039 ; C3.2@8.037,4.941 8.939,4.039 9.83,4.039 ; U1.43 U1.44 ; 9.83,4.039 11.862,4.039 ; 9.83,4.039 10.137,3.731 C2.1 11.684,3.453 ; 11.684,3.453 11.862,3.631 11.862,4.039 ; 11.862,4.039 14.478,4.039 ; 11.862,4.039 14.478,4.039 ; 12.903,56.49 14.884,56.49 19.268,52.106 19.268,51.649 ; 12.903,56.49 15.24,56.49 15.748,55.982 15.748,55.169 19.268,51.649 ; 29.464,18.948 29.464,19.692 30.208,19.692 ; 29.464,18.948 29.464,17.292 U2.27@31.547,17.292 ; 29.464,18.948 30.208,19.692 ; 30.48,10.892 29.875,11.497 29.875,12.7 30.467,13.292 U2.37@31.547,13.292 ; U2.37@31.547,13.292 U2.35@31.547,14.092 ; U2.37@31.547,13.292 U2.35@31.547,14.092 ; U2.35@31.547,14.092 U2.35 v1(33.313,14.092) 33.32,14.092 v1@33.96,14.732 ; U2.29@31.547,16.492 U2.27@31.547,17.292 ; U2.29@31.547,16.492 U2.27@31.547,17.292 ; U2.29@31.547,16.492 U2.29 33.216,16.492 ; U2.15@32.512,25.292 v1(32.512,23.724) U2.15@32.512,25.292 ; U2.15@32.512,25.292 32.757,25.292 36.385,21.664 36.385,18.288 36.981,17.692 37.274,17.692 ; 33.047,42.164 33.604,42.164 ; 33.047,42.164 33.604,42.164 ; 33.216,16.492 v1@33.952,15.756 ; 33.216,16.492 33.341,16.492 33.952,15.881 v1@33.952,15.756 ; 33.528,44.72 34.036,44.212 34.036,43.667 ; 33.528,44.72 C5.2 33.047,44.361 33.233,44.175 33.528,44.175 34.036,43.667 ; 33.528,44.72 34.417,45.609 ; 33.528,48.006 33.655,48.006 34.417,47.244 v1@34.417,46.928 ; 33.528,48.006 34.174,47.36 34.174,47.171 v1@34.417,46.928 ; 33.604,42.164 34.036,42.596 ; v1@33.952,15.756 v1@33.96,15.748 ; v1@33.96,14.732 v1@33.96,15.748 ; v1@33.96,14.732 v1@33.96,15.748 ; 34.036,42.596 34.036,43.667 ; 34.036,42.596 34.036,43.667 ; 34.417,45.609 v1@34.417,46.928 ; 34.417,45.609 v1@34.417,46.928 ; 37.154,23.851 36.805,23.851 32.963,27.692 U2.9 v1(33.313,27.692) 37.154,23.851 ; 37.154,23.851 41.554,23.851 ; 37.274,17.692 U2.26 v1@41.148,17.692 ; 38.506,12.446 38.506,14.097 ; 38.506,12.446 38.506,12.319 38.733,12.092 U2.40 U2.40@40.588,12.092 ; 38.506,12.446 38.735,12.217 ; 38.506,14.097 38.633,14.224 ; 38.633,14.224 U2.34@40.488,14.224 ; 38.633,14.224 U2.34@40.488,14.224 ; 38.735,12.217 U2.40@40.462,12.217 ; 38.735,12.217 U2.40@40.462,12.217 ; U2.40@40.462,12.217 U2.40@40.588,12.092 ; U2.34@40.488,14.224 41.504,15.24 v1@41.504,17.336 ; U2.40@40.588,12.092 40.842,12.092 40.996,11.938 40.996,11.684 ; U2.40@40.588,12.092 40.996,11.684 ; v1@41.148,17.692 v1@41.504,17.336 ; v1@41.148,17.692 v1@41.504,17.336 ; 41.554,23.851 43.637,25.933 43.637,28.956 42.901,29.692 ; 45.862,42.164 46.48,41.546 USIM1.C11 48.438,41.546 48.522,41.631 ; 45.862,42.164 45.862,42.6 ; 45.862,42.6 46.736,41.726 ; 46.736,41.726 USIM1.C12@48.912,41.726 ; 46.736,41.726 USIM1.C12@48.912,41.726 ; 48.522,41.631 USIM1.C12@48.912,41.631 ; 48.522,41.631 USIM1.C12@48.912,41.631 ; USIM1.C12@48.912,41.631 USIM1.C12@48.912,41.726 ; USIM1.C12@48.912,41.726 v1(51.95,41.726) ; USIM1.C12@48.912,41.726 v1(51.95,41.726) ; v1(51.95,41.726) USIM1.C13 56.442,41.726 ; 56.442,41.726 USIM1.C14 USIM1.C14@58.09,41.726 ; USIM1.C14@58.09,41.726 v1(58.09,38.786) USIM1.C14@58.09,41.726 ; USIM1.C14@58.09,41.726 60.833,41.726 61.012,41.905 USIM1.C15 61.012,44.641 ; v1(67.412,40.894) 67.412,43.192 ; v1(67.412,40.894) 67.412,43.192 ; v1(67.412,40.894) 67.412,43.192 ; 67.412,43.192 66.894,43.71 C7.2 67.285,44.069 67.412,43.942 67.412,43.192 ; 82.677,48.26 v1@82.677,50.597 ; 82.677,48.26 v1@82.677,50.597 ; v1@82.677,50.597 82.677,51.816 ; v1@82.677,50.597 82.677,51.816 ; v1@82.677,50.597 83.022,50.597 U3.1@83.987,51.562 ; 82.677,51.816 82.931,51.562 U3.1@83.987,51.562 ; 107.899,56.947 108.687,56.947 109.474,56.159 109.474,55.372 ; 107.899,56.947 109.474,55.372 ; 107.925,49.759 109.474,51.308 109.474,55.372
GSM_DTR: U1.34 U2.31 | length 33.8
  Top Layer w0.203: U1.34 8.917,28.067 18.034,18.95 18.034,16.129 18.161,16.002 20.193,16.002 20.503,15.692 U2.31
GSM_LED_WWAN#: U1.31 U2.42 | length 41.2
  Top Layer w0.203: v1(12.727,26.492) U1.31 ; v1(37.743,15.369) 37.743,12.157 38.608,11.292 U2.42
  Bottom Layer w0.203: v1(12.727,26.492) 15.415,23.804 29.307,23.804 v1(37.743,15.369)
GSM_PERST#: U1.32 U2.22 | length 39.4
  Top Layer w0.203: U1.32 v1(11.457,33.985) ; U2.22 41.492,19.292 v1(41.504,19.304)
  Bottom Layer w0.203: v1(11.457,33.985) 19.56,25.883 34.925,25.883 v1(41.504,19.304)
GSM_RI: U1.35 U2.17 | length 34.9
  Top Layer w0.203: v1(7.647,27) U1.35 ; v1(29.54,20.955) 29.877,21.292 U2.17
  Bottom Layer w0.203: v1(7.647,27) 6.731,26.084 6.731,24.333 10.109,20.955 v1(29.54,20.955)
GSM_W_DISABLE#: U1.33 U2.20 | length 36.1
  Top Layer w0.203: v1(10.185,30.963) 10.187,30.964 U1.33 ; v1(37.541,20.092) U2.20
  Bottom Layer w0.203: v1(10.185,30.963) 17.013,24.135 24.405,24.135 25.034,24.763 32.87,24.763 v1(37.541,20.092)
GSM_WAKE#: U1.30 U2.1 | length 23.9
  Top Layer w0.203: U1.30 v1(13.997,33.985) ; U2.1 33.319,30.892 v1(33.325,30.886)
  Bottom Layer w0.203: v1(13.997,33.985) 30.226,33.985 v1(33.325,30.886)
MCU_CTS: U1.18 U2.25 | length 21.2
  Top Layer w0.203: U1.18 U1.18@19.355,20.547 ; U2.25 31.749,18.29 32.573,18.29 33.11,18.828 33.11,21.823 32.782,22.151 22.659,22.151 21.082,20.574 19.612,20.574 19.482,20.704 19.482,21.082 19.355,21.082 ; U1.18@19.355,20.547 19.355,21.082 ; U1.18@19.355,20.547 19.355,21.082
MCU_RTS: U1.17 U2.23 | length 18.6
  Top Layer w0.203: U1.17 19.585,19.277 19.839,19.531 20.547,19.531 22.837,21.821 32.646,21.821 32.78,21.687 32.78,19.297 32.573,19.09 31.749,19.09 U2.23
MCU_RXD: U1.11 U2.13 | length 67.8
  Top Layer w0.203: U1.11 13.997,13.816 25.908,1.905 42.553,1.905 42.672,2.024 42.672,22.36 42.553,22.479 36.449,22.479 32.864,26.064 31.579,26.064 U2.13
MCU_TXD: U1.10 U2.11 | length 70.9
  Top Layer w0.203: U1.10@12.727,14.961 12.727,13.943 25.146,1.524 42.934,1.524 43.053,1.643 43.053,22.741 42.934,22.86 36.703,22.86 32.737,26.826 31.617,26.826 U2.11
NetC2_2: C2.2 R1.2 SW1.2 U1.3 | length 51
  Top Layer w0.203: R1.2 3.81,12.979 3.837,13.006 3.837,13.716 ; U1.3 3.837,13.716 ; SW1.2 7.838,39.228 v1(7.976,39.091) ; v1(9.347,12.649) 9.347,10.4 8.636,9.689 ; C2.2 10.109,4.953 9.474,5.588 9.474,9.144 8.929,9.689 8.636,9.689 ; 3.837,13.716 4.548,13.005 5.156,13.005 7.022,11.139 7.493,11.139 7.493,9.689 8.636,9.689
  Bottom Layer w0.203: v1(7.976,39.091) 6.401,37.516 6.401,23.901 9.347,20.955 v1(9.347,12.649)
NetC4_1: C4.1 R6.2 R9.2 TVS1.6 USIM1.C7 | length 77.9
  Top Layer w0.203: R6.2 R6.2@27.432,48.006 ; v1(30.48,46.558) 31.161,46.558 31.847,47.244 C4.1 ; TVS1.6 v1(42.621,45.908) ; v1(51.968,43.942) v1(51.968,45.432) 51.968,50.108 52.832,50.971 USIM1.C7 ; R9.2 v1(67.869,52.324) ; R6.2@27.432,48.006 C4.1 ; R6.2@27.432,48.006 C4.1
  Bottom Layer w0.203: v1(30.48,46.558) 30.48,42.012 30.988,41.504 42.723,41.504 43.231,42.012 43.231,45.298 ; v1(42.621,45.908) 43.231,45.298 ; v1(51.968,43.942) 44.587,43.942 43.231,45.298 ; v1(51.968,45.432) 55.871,41.529 60.782,41.529 67.869,48.616 v1(67.869,52.324)
NetC5_1: C5.1 R7.2 TVS1.5 USIM1.C3 | length 40
  Top Layer w0.203: R7.2 29.642,44.718 29.643,44.72 C5.1 v1(31.847,46.001) ; v1(39.878,44.958) TVS1.5 ; v1(54.102,50.825) USIM1.C3
  Bottom Layer w0.203: v1(31.847,46.001) 36.798,50.952 41.656,50.952 ; v1(39.878,44.958) 39.878,49.174 41.656,50.952 ; v1(54.102,50.825) 53.645,50.368 46.736,50.368 46.152,50.952 41.656,50.952
NetC6_1: C6.1 R8.2 TVS1.4 USIM1.C2 | length 47.7
  Top Layer w0.203: R8.2 29.591,41.783 29.718,41.656 C6.1 31.847,42.164 32.888,43.205 v1(33.172,43.205) ; TVS1.4 42.123,44.008 v1(42.367,43.764) ; v1(51.562,51.232) USIM1.C2
  Bottom Layer w0.203: v1(33.172,43.205) 33.731,43.764 v1(42.367,43.764) 41.504,44.628 41.504,46.228 42.062,46.787 44.298,46.787 45.212,45.872 45.212,44.399 45.339,44.272 48.387,44.272 50.698,46.584 54.356,46.584 54.966,47.193 54.966,52.324 54.458,52.832 53.162,52.832 v1(51.562,51.232)
NetC7_1: C7.1 R9.1 TVS1.3 U2.8 USIM1.C1 | length 83.7
  Top Layer w0.203: U2.8 38.735,28.092 38.379,28.448 ; C7.1 65.694,46.482 66.167,46.955 R9.1 66.167,50.216 63.856,52.527 63.856,56.896 63.017,57.734 52.324,57.734 52.019,57.429 52.019,54.61 49.86,52.451 USIM1.C1 49.022,51.308 48.006,50.292 47.269,50.292 47.015,50.038 47.015,49.022 44.221,46.228 44.221,43.686 43.172,42.636 40.426,42.636 39.054,44.008 TVS1.3 TVS1.3@38.379,44.008 ; 38.379,28.448 TVS1.3@38.379,44.008 ; 38.379,28.448 TVS1.3@38.379,44.008
NetC10_2: C10.2 R10.1 U3.6 | length 29.8
  Top Layer w0.203: U3.6 78.156,54.102 77.394,54.864 77.394,55.88 78.207,56.693 95.504,56.693 96.114,56.083 96.114,54.473 95.885,54.244 R10.1 95.631,52.248 95.758,52.121 C10.2
NetC11_1: C11.1 U3.7 | length 8.5
  Top Layer w0.203: C11.1 77.343,53.467 77.978,52.832 U3.7
NetC11_2: C11.2 L1.1 U3.8 | length 12.3
  Top Layer w0.203: L1.1 C11.2 75.895,51.967 76.3,51.562 U3.8
NetJ1_1: J1.1 U1.25 | length 30.4
  Top Layer w0.203: J1.1 18.009,52.095 18.009,44.704 21.109,41.604 21.109,30.427 20.118,29.437 U1.25
NetJ1_2: J1.2 U1.19 | length 44.3
  Top Layer w0.203: J1.2 18.161,56.769 22.352,56.769 22.962,56.159 22.962,51.943 22.657,51.638 22.657,22.631 21.842,21.817 U1.19
NetJ1_3: J1.3 U1.21 | length 34.1
  Top Layer w0.203: U1.21 20.903,24.357 21.439,24.893 21.439,53.745 J1.3
NetJ1_4: J1.4 U1.20 | length 35.1
  Top Layer w0.203: U1.20 21.336,23.087 22.098,23.849 J1.4
NetJ1_7: J1.7 U1.23 | length 34
  Top Layer w0.203: U1.23 v1(20.574,26.897) ; v1(24.13,30.453) 24.13,50.038 J1.7
  Bottom Layer w0.203: v1(20.574,26.897) v1(24.13,30.453)
NetJ1_8: J1.8 U1.22 | length 42.4
  Top Layer w0.203: v1(17.551,25.629) 17.553,25.627 U1.22 ; v1(23.546,25.019) 24.994,26.467 24.994,49.074 31.546,55.626 J1.8
  Bottom Layer w0.203: v1(17.551,25.629) 18.161,25.019 v1(23.546,25.019)
NetJ2_2: J2.2 U1.37 | length 24.4
  Top Layer w0.203: U1.37 5.107,34.368 7.061,36.322 7.061,54.026 J2.2
NetJ2_3: J2.3 U1.36 | length 24.4
  Top Layer w0.203: U1.36 6.377,34.925 8.956,37.504 8.956,54.671 J2.3
NetLS1_1: LS1.1 U1.15 | length 84.4
  Top Layer w0.203: U1.15 v1(26.595,16.737)
  Bottom Layer w0.203: v1(26.595,16.737) 30.124,13.208 96.941,13.208 LS1.1
NetR2_2: R2.2 U1.8 | length 4.3
  Top Layer w0.203: U1.8 10.187,13.41 11.049,12.548 R2.2
NetR3_1: R3.1 U1.38 | length 4
  Top Layer w0.203: U1.38 3.837,35.159 4.445,35.767 R3.1
NetR4_1: R4.1 SW2.1 U1.27 | length 11.8
  Top Layer w0.203: SW2.1 14.768,37.084 15.623,36.229 R4.1 18.415,35.252 17.807,34.644 U1.27
NetR6_1: R6.1 U2.10 | length 33.7
  Top Layer w0.203: R6.1 R6.1@25.982,48.26 ; U2.10 38.608,27.292 38.011,27.889 38.011,35.115 35.56,37.567 35.56,48.006 34.747,48.819 26.873,48.819 26.314,48.26 ; R6.1@25.982,48.26 26.314,48.26 ; R6.1@25.982,48.26 26.314,48.26
NetR7_1: R7.1 U2.12 | length 28.3
  Top Layer w0.203: v1(26.019,43.002) R7.1 ; U2.12 42.367,26.492 v1(42.774,26.899)
  Bottom Layer w0.203: v1(26.019,43.002) 26.67,43.002 v1(42.774,26.899)
NetR8_1: R8.1 U2.14 | length 24.7
  Top Layer w0.203: R8.1 26.019,40.834 v1(26.67,40.183) ; v1(36.703,25.692) U2.14
  Bottom Layer w0.203: v1(26.67,40.183) 28.524,40.183 36.703,32.004 v1(36.703,25.692)
NetR10_2: R10.2 U3.4 | length 10.6
  Top Layer w0.203: U3.4 90.17,55.372 90.566,54.976 R10.2
NetR11_2: R11.2 R12.1 U3.5 | length 40.9
  Top Layer w0.203: v1(78.257,55.372) U3.5 ; R11.2 v1(101.234,46.279) ; R12.1 v1(108.966,46.38)
  Bottom Layer w0.203: v1(78.257,55.372) 92.141,55.372 v1(101.234,46.279) 104.14,46.279 104.521,45.898 108.483,45.898 v1(108.966,46.38)
NetTVS1_1: TVS1.1 U2.44 USIM1.SW | length 85.6
  Top Layer w0.203: TVS1.1 TVS1.1@38.379,45.908 ; U2.44 37.412,10.492 35.458,12.446 35.458,22.123 34.849,22.733 30.937,22.733 30.302,23.368 30.302,39.98 29.235,41.046 26.924,41.046 26.67,41.3 26.67,42.113 26.924,42.367 26.924,43.739 26.746,43.917 26.746,45.113 25.428,46.431 25.428,48.812 26.314,48.812 26.652,49.149 35.138,49.149 TVS1.1@38.379,45.908 ; USIM1.SW 39.116,52.626 38.379,51.889 ; TVS1.1@38.379,45.908 38.379,51.889 ; TVS1.1@38.379,45.908 38.379,51.889
USB_DM: U1.13 U2.36 | length 45.2
  Top Layer w0.203: U1.13 16.751,14.758 16.751,14.037 28.502,2.286 42.172,2.286 42.291,2.405 42.291,13.522 42.172,13.641 39.802,13.641 U2.36
USB_DP: U1.14 U2.38 | length 42.1
  Top Layer w0.203: U1.14 17.807,13.837 28.977,2.667 41.791,2.667 41.91,2.786 41.91,12.773 41.791,12.892 U2.38
Vin: C8.1 C9.1 J3.1 U3.2 U3.3 | length 33.1
  Top Layer w0.203: U3.2 U3.3 89.332,54.102 94.488,48.946 96.926,48.946 99.568,51.587 101.286,51.587 101.565,51.308 ; C9.1 101.565,51.308 ; C8.1 101.588,53.987 ; J3.1 102.108,53.467 101.588,53.987 ; 101.565,51.308 101.565,53.964 101.588,53.987
pads on no net: SW1.1 SW1.4 SW2.2 SW2.3 U1.4 U1.5 U1.6 U1.7 U1.9 U1.12 U1.16 U1.24 U1.26 U1.28 U1.29 U1.39 U2.3 U2.5 U2.6 U2.7 U2.16 U2.19 U2.24 U2.28 U2.30 U2.32 U2.33 U2.45 U2.46 U2.47 U2.48 U2.49 U2.51 U2.MH1 U2.MH2 U2.MP1 U2.MP2 USIM1. USIM1.C6

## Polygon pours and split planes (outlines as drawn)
GND on GND Plane (split plane): 116.203,0.51 0.51,0.51 0.51,57.91 116.203,57.91
+3V3 on PWR Plane (split plane): 116.203,0.51 0.51,0.51 0.51,57.91 116.203,57.91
